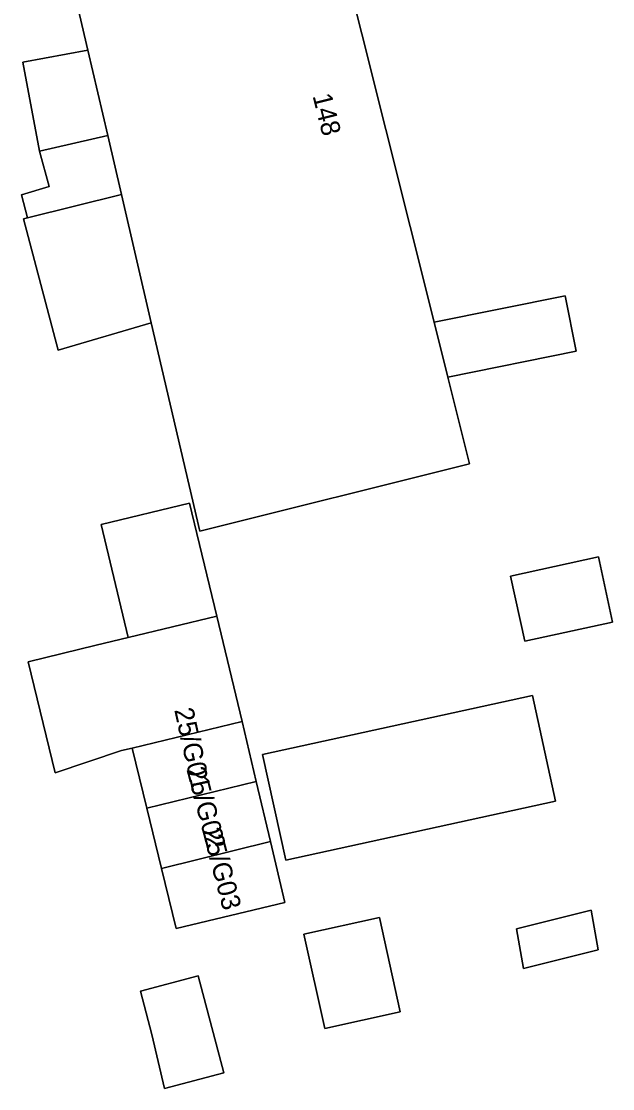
# Model space of a CAD drawing. Extents: x 159262 to 160143, y 383399 to 384319.
# Drawn here: x 159695.4 to 159726.2, y 383669.9 to 383725.6 of the extents above; entities that cross this region are included whole.
import ezdxf

# ---------------------------------------------------------------- set-up
doc = ezdxf.new("R2010")
doc.units = 0
for name, color, linetype in [('IMGEO_Erf', 7, 'Continuous'), ('IMGEO_Pand', 7, 'Continuous'), ('IMGEO_Pand_nummerreeks', 7, 'Continuous')]:
    doc.layers.add(name, color=color, linetype=linetype)

msp = doc.modelspace()

# ---------------------------------------------------------------- linework, layer by layer
at = {"layer": 'IMGEO_Erf'}
for points in [[(159704.661, 383698.968), (159702.131, 383709.846), (159697.283, 383708.423), (159695.46, 383715.276), (159695.676, 383715.329), (159695.357, 383716.526), (159696.815, 383716.954), (159696.296, 383718.799), (159695.429, 383723.442), (159698.821, 383724.076), (159695.804, 383737.047), (159709.334, 383739.989), (159716.877, 383709.874), (159723.707, 383711.244), (159724.286, 383708.358), (159717.593, 383707.015), (159718.726, 383702.49)], [(159703.438, 383678.242), (159702.668, 383681.378), (159701.899, 383684.513), (159701.129, 383687.649), (159700.585, 383687.518), (159697.112, 383686.354), (159695.711, 383692.16), (159699.258, 383693.016), (159700.934, 383693.421), (159699.511, 383699.319), (159704.118, 383700.431), (159705.542, 383694.533), (159706.869, 383689.035), (159707.603, 383685.914), (159708.342, 383682.77), (159709.089, 383679.592)], [(159721.615, 383693.225), (159720.872, 383696.625), (159725.447, 383697.625), (159726.19, 383694.225)], [(159709.14, 383681.807), (159707.934, 383687.319), (159722.011, 383690.399), (159723.216, 383684.886)], [(159721.534, 383676.153), (159721.175, 383678.23), (159725.072, 383679.196), (159725.431, 383677.119)], [(159711.178, 383673.015), (159710.092, 383677.941), (159714.024, 383678.807), (159715.11, 383673.882)], [(159702.815, 383669.882), (159702.167, 383672.705), (159701.565, 383674.973), (159704.576, 383675.773), (159705.922, 383670.707)]]:
    msp.add_lwpolyline(points, close=True, dxfattribs=at)
at = {"layer": 'IMGEO_Pand'}
for points in [[(159709.334, 383739.989), (159695.804, 383737.047), (159698.821, 383724.076), (159699.858, 383719.619), (159700.576, 383716.532), (159702.131, 383709.846), (159704.661, 383698.968), (159718.726, 383702.49), (159717.593, 383707.015), (159716.877, 383709.874)], [(159698.821, 383724.076), (159695.429, 383723.442), (159696.296, 383718.799), (159699.858, 383719.619)], [(159699.858, 383719.619), (159696.296, 383718.799), (159696.815, 383716.954), (159695.357, 383716.526), (159695.676, 383715.329), (159700.576, 383716.532)], [(159700.576, 383716.532), (159695.676, 383715.329), (159695.46, 383715.276), (159697.283, 383708.423), (159702.131, 383709.846)], [(159716.877, 383709.874), (159717.593, 383707.015), (159724.286, 383708.358), (159723.707, 383711.244)], [(159700.934, 383693.421), (159705.542, 383694.533), (159704.118, 383700.431), (159699.511, 383699.319)], [(159720.872, 383696.625), (159721.615, 383693.225), (159726.19, 383694.225), (159725.447, 383697.625)], [(159705.542, 383694.533), (159700.934, 383693.421), (159699.258, 383693.016), (159695.711, 383692.16), (159697.112, 383686.354), (159700.585, 383687.518), (159701.129, 383687.649), (159706.869, 383689.035)], [(159722.011, 383690.399), (159707.934, 383687.319), (159709.14, 383681.807), (159723.216, 383684.886)], [(159701.899, 383684.513), (159707.603, 383685.914), (159706.869, 383689.035), (159701.129, 383687.649)], [(159701.899, 383684.513), (159702.668, 383681.378), (159708.342, 383682.77), (159707.603, 383685.914)], [(159708.342, 383682.77), (159702.668, 383681.378), (159703.438, 383678.242), (159709.089, 383679.592)], [(159721.175, 383678.23), (159721.534, 383676.153), (159725.431, 383677.119), (159725.072, 383679.196)], [(159710.092, 383677.941), (159711.178, 383673.015), (159715.11, 383673.882), (159714.024, 383678.807)], [(159702.815, 383669.882), (159705.922, 383670.707), (159704.576, 383675.773), (159701.565, 383674.973), (159702.167, 383672.705)]]:
    msp.add_lwpolyline(points, close=True, dxfattribs=at)

# ---------------------------------------------------------------- texts
at = {"layer": 'IMGEO_Pand_nummerreeks'}
for s, rotation, p in [('148', 284.0602, (159710.537, 383721.688)), ('25/G01', 282.4174, (159703.326, 383689.647)), ('25/G02', 284.6419, (159703.96, 383686.538)), ('25/G03', 284.5167, (159704.783, 383683.371))]:
    msp.add_text(s, height=1, rotation=rotation, dxfattribs=at).set_placement(p)

doc.saveas('drawing.dxf')
